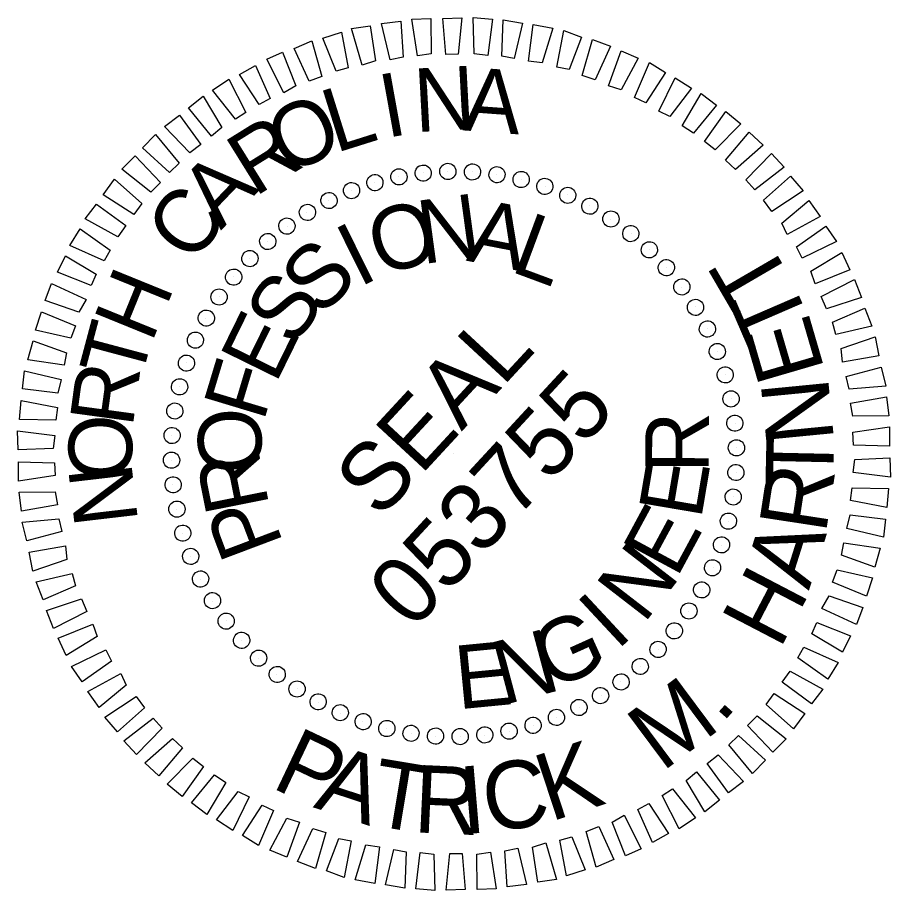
# Model space of a CAD drawing. Extents: x 1768274 to 1769121, y 999922 to 1000687.
# Drawn here: x 1769000.709 to 1769001.89, y 1000302.108 to 1000303.288 of the extents above; entities that cross this region are included whole.
import ezdxf

# ---------------------------------------------------------------- set-up
doc = ezdxf.new("R2010")
doc.units = 0
doc.layers.add('E_NCDOT_Terrain_Model_Void', color=7, linetype='Continuous')

msp = doc.modelspace()

# ---------------------------------------------------------------- linework, layer by layer
at = {"layer": 'E_NCDOT_Terrain_Model_Void'}
for p, q in [((1769001.2586, 1000303.0787), (1769001.2586, 1000303.0787)), ((1769001.2914, 1000303.0805), (1769001.2914, 1000303.0805)), ((1769001.3254, 1000303.0802), (1769001.3254, 1000303.0802)), ((1769001.3579, 1000303.0761), (1769001.3579, 1000303.0761)), ((1769001.1928, 1000303.0658), (1769001.1928, 1000303.0658)), ((1769001.2254, 1000303.073), (1769001.2254, 1000303.073)), ((1769001.391, 1000303.0693), (1769001.391, 1000303.0693)), ((1769001.1614, 1000303.0543), (1769001.1614, 1000303.0543)), ((1769001.4232, 1000303.0603), (1769001.4232, 1000303.0603)), ((1769001.1307, 1000303.0413), (1769001.1307, 1000303.0413)), ((1769001.4538, 1000303.0486), (1769001.4538, 1000303.0486)), ((1769001.4835, 1000303.0336), (1769001.4835, 1000303.0336)), ((1769001.1011, 1000303.025), (1769001.1011, 1000303.025)), ((1769001.5123, 1000303.0153), (1769001.5123, 1000303.0153)), ((1769001.0744, 1000303.0062), (1769001.0744, 1000303.0062)), ((1769001.5394, 1000302.9964), (1769001.5394, 1000302.9964)), ((1769001.0482, 1000302.9857), (1769001.0482, 1000302.9857)), ((1769001.5646, 1000302.9742), (1769001.5646, 1000302.9742)), ((1769001.0238, 1000302.9627), (1769001.0238, 1000302.9627)), ((1769001.5876, 1000302.9498), (1769001.5876, 1000302.9498)), ((1769001.0016, 1000302.9375), (1769001.0016, 1000302.9375)), ((1769001.6081, 1000302.9237), (1769001.6081, 1000302.9237)), ((1769000.9827, 1000302.9104), (1769000.9827, 1000302.9104)), ((1769001.6269, 1000302.8969), (1769001.6269, 1000302.8969)), ((1769000.9644, 1000302.8816), (1769000.9644, 1000302.8816)), ((1769001.6432, 1000302.8674), (1769001.6432, 1000302.8674)), ((1769000.9494, 1000302.8519), (1769000.9494, 1000302.8519)), ((1769001.6562, 1000302.8366), (1769001.6562, 1000302.8366)), ((1769000.9377, 1000302.8213), (1769000.9377, 1000302.8213)), ((1769001.6677, 1000302.8052), (1769001.6677, 1000302.8052)), ((1769000.9287, 1000302.7891), (1769000.9287, 1000302.7891)), ((1769001.6749, 1000302.7726), (1769001.6749, 1000302.7726)), ((1769000.9219, 1000302.756), (1769000.9219, 1000302.756)), ((1769001.6805, 1000302.7394), (1769001.6805, 1000302.7394)), ((1769000.9178, 1000302.7235), (1769000.9178, 1000302.7235)), ((1769001.2999, 1000302.6981), (1769001.2999, 1000302.6981)), ((1769001.6824, 1000302.7066), (1769001.6824, 1000302.7066)), ((1769000.9175, 1000302.6895), (1769000.9175, 1000302.6895)), ((1769001.6821, 1000302.6726), (1769001.6821, 1000302.6726)), ((1769000.9194, 1000302.6567), (1769000.9194, 1000302.6567)), ((1769001.678, 1000302.6401), (1769001.678, 1000302.6401)), ((1769000.925, 1000302.6235), (1769000.925, 1000302.6235)), ((1769001.6712, 1000302.607), (1769001.6712, 1000302.607)), ((1769000.9322, 1000302.5909), (1769000.9322, 1000302.5909)), ((1769001.6622, 1000302.5748), (1769001.6622, 1000302.5748)), ((1769000.9437, 1000302.5595), (1769000.9437, 1000302.5595)), ((1769001.6505, 1000302.5442), (1769001.6505, 1000302.5442)), ((1769000.9567, 1000302.5288), (1769000.9567, 1000302.5288)), ((1769001.6355, 1000302.5145), (1769001.6355, 1000302.5145)), ((1769000.973, 1000302.4992), (1769000.973, 1000302.4992)), ((1769001.6172, 1000302.4857), (1769001.6172, 1000302.4857)), ((1769000.9918, 1000302.4725), (1769000.9918, 1000302.4725)), ((1769001.5983, 1000302.4586), (1769001.5983, 1000302.4586)), ((1769001.0123, 1000302.4463), (1769001.0123, 1000302.4463)), ((1769001.5761, 1000302.4334), (1769001.5761, 1000302.4334)), ((1769001.0353, 1000302.4219), (1769001.0353, 1000302.4219)), ((1769001.5517, 1000302.4104), (1769001.5517, 1000302.4104)), ((1769001.0605, 1000302.3997), (1769001.0605, 1000302.3997)), ((1769001.5255, 1000302.3899), (1769001.5255, 1000302.3899)), ((1769001.0876, 1000302.3808), (1769001.0876, 1000302.3808)), ((1769001.4988, 1000302.3711), (1769001.4988, 1000302.3711)), ((1769001.1164, 1000302.3625), (1769001.1164, 1000302.3625)), ((1769001.4692, 1000302.3548), (1769001.4692, 1000302.3548)), ((1769001.1461, 1000302.3475), (1769001.1461, 1000302.3475)), ((1769001.4385, 1000302.3418), (1769001.4385, 1000302.3418)), ((1769001.1767, 1000302.3358), (1769001.1767, 1000302.3358)), ((1769001.4071, 1000302.3303), (1769001.4071, 1000302.3303)), ((1769001.2089, 1000302.3268), (1769001.2089, 1000302.3268)), ((1769001.242, 1000302.32), (1769001.242, 1000302.32)), ((1769001.3413, 1000302.3175), (1769001.3413, 1000302.3175)), ((1769001.3745, 1000302.3231), (1769001.3745, 1000302.3231)), ((1769001.2745, 1000302.3159), (1769001.2745, 1000302.3159)), ((1769001.3085, 1000302.3156), (1769001.3085, 1000302.3156))]:
    msp.add_line(p, q, dxfattribs=at)
for points in [[(1769001.2508, 1000303.2363), (1769001.2429, 1000303.2861), (1769001.2687, 1000303.2871), (1769001.269, 1000303.2392)], [(1769001.289, 1000303.2383), (1769001.2849, 1000303.2867), (1769001.3107, 1000303.2877), (1769001.3057, 1000303.2385)], [(1769001.3272, 1000303.2393), (1769001.3258, 1000303.2883), (1769001.3518, 1000303.2861), (1769001.3456, 1000303.2368)], [(1769001.1758, 1000303.2237), (1769001.1614, 1000303.2732), (1769001.1866, 1000303.2769), (1769001.1939, 1000303.2298)], [(1769001.2138, 1000303.2311), (1769001.2021, 1000303.2802), (1769001.2279, 1000303.2834), (1769001.2314, 1000303.2345)], [(1769001.3645, 1000303.2359), (1769001.3664, 1000303.2851), (1769001.3924, 1000303.2807), (1769001.3814, 1000303.2328)], [(1769001.4009, 1000303.2293), (1769001.4071, 1000303.2786), (1769001.4337, 1000303.2737), (1769001.4193, 1000303.2268)], [(1769001.1405, 1000303.2158), (1769001.1226, 1000303.2604), (1769001.1476, 1000303.2684), (1769001.157, 1000303.2202)], [(1769001.439, 1000303.2211), (1769001.4483, 1000303.2705), (1769001.4724, 1000303.2617), (1769001.4558, 1000303.2179)], [(1769001.1039, 1000303.202), (1769001.0838, 1000303.2465), (1769001.1076, 1000303.2566), (1769001.1214, 1000303.2086)], [(1769001.4734, 1000303.21), (1769001.4871, 1000303.2585), (1769001.5117, 1000303.2493), (1769001.4908, 1000303.2042)], [(1769001.07, 1000303.1866), (1769001.0466, 1000303.2321), (1769001.0678, 1000303.2415), (1769001.0858, 1000303.1959)], [(1769001.509, 1000303.1958), (1769001.526, 1000303.2433), (1769001.549, 1000303.2335), (1769001.5259, 1000303.1905)], [(1769001.5441, 1000303.1799), (1769001.5643, 1000303.2276), (1769001.5859, 1000303.2139), (1769001.5595, 1000303.173)], [(1769001.0366, 1000303.1707), (1769001.0097, 1000303.2112), (1769001.0313, 1000303.2234), (1769001.0514, 1000303.1789)], [(1769001.0045, 1000303.1506), (1769000.9733, 1000303.1898), (1769000.9954, 1000303.2047), (1769001.0182, 1000303.1598)], [(1769001.5771, 1000303.1618), (1769001.5991, 1000303.2069), (1769001.6212, 1000303.1926), (1769001.592, 1000303.1543)], [(1769000.972, 1000303.1278), (1769000.9408, 1000303.1659), (1769000.9607, 1000303.1818), (1769000.9861, 1000303.1396)], [(1769001.6087, 1000303.142), (1769001.6344, 1000303.1856), (1769001.655, 1000303.1697), (1769001.6241, 1000303.1318)], [(1769000.9427, 1000303.1051), (1769000.9084, 1000303.1409), (1769000.9288, 1000303.1563), (1769000.9573, 1000303.1164)], [(1769001.6386, 1000303.1205), (1769001.6677, 1000303.161), (1769001.6878, 1000303.1446), (1769001.6531, 1000303.1093)], [(1769001.6671, 1000303.0953), (1769001.699, 1000303.1332), (1769001.7181, 1000303.1156), (1769001.6805, 1000303.0828)], [(1769000.9152, 1000303.0786), (1769000.8788, 1000303.1122), (1769000.8964, 1000303.1302), (1769000.9281, 1000303.0915)], [(1769000.8898, 1000303.0523), (1769000.8508, 1000303.0831), (1769000.8685, 1000303.1011), (1769000.9028, 1000303.0652)], [(1769001.6946, 1000303.0688), (1769001.7293, 1000303.1042), (1769001.7467, 1000303.086), (1769001.7069, 1000303.0553)], [(1769001.7188, 1000303.0412), (1769001.7553, 1000303.0739), (1769001.7722, 1000303.0541), (1769001.7297, 1000303.026)], [(1769000.8667, 1000303.0217), (1769000.8252, 1000303.0487), (1769000.8406, 1000303.0698), (1769000.8775, 1000303.0367)], [(1769001.7432, 1000303.0104), (1769001.7797, 1000303.0409), (1769001.7951, 1000303.0194), (1769001.7508, 1000302.995)], [(1769000.8453, 1000302.9918), (1769000.8012, 1000303.0159), (1769000.8166, 1000303.0359), (1769000.856, 1000303.0068)], [(1769000.8266, 1000302.9592), (1769000.7805, 1000302.9801), (1769000.7942, 1000303.0027), (1769000.8347, 1000302.9736)], [(1769001.7633, 1000302.9783), (1769001.8027, 1000303.0062), (1769001.8175, 1000302.9853), (1769001.771, 1000302.9629)], [(1769001.7824, 1000302.9451), (1769001.8246, 1000302.9704), (1769001.8352, 1000302.9471), (1769001.7885, 1000302.9281)], [(1769000.809, 1000302.9257), (1769000.7636, 1000302.9438), (1769000.7746, 1000302.9658), (1769000.816, 1000302.941)], [(1769001.7967, 1000302.9111), (1769001.8416, 1000302.9339), (1769001.8512, 1000302.9095), (1769001.8038, 1000302.8942)], [(1769000.7927, 1000302.89), (1769000.7468, 1000302.9054), (1769000.7556, 1000302.9284), (1769000.8022, 1000302.9071)], [(1769000.7817, 1000302.8545), (1769000.7338, 1000302.8656), (1769000.742, 1000302.8901), (1769000.788, 1000302.8715)], [(1769001.8121, 1000302.8761), (1769001.8556, 1000302.8951), (1769001.8651, 1000302.8707), (1769001.8165, 1000302.8596)], [(1769000.7728, 1000302.818), (1769000.7235, 1000302.8253), (1769000.7306, 1000302.8509), (1769000.776, 1000302.8349)], [(1769001.8237, 1000302.8405), (1769001.8695, 1000302.8563), (1769001.8748, 1000302.8306), (1769001.8255, 1000302.8222)], [(1769001.8306, 1000302.803), (1769001.8776, 1000302.8156), (1769001.884, 1000302.79), (1769001.8345, 1000302.7859)], [(1769000.7641, 1000302.7805), (1769000.7164, 1000302.7862), (1769000.7192, 1000302.8105), (1769000.7687, 1000302.799)], [(1769000.7612, 1000302.7437), (1769000.7121, 1000302.7445), (1769000.7143, 1000302.7705), (1769000.7638, 1000302.7611)], [(1769001.8364, 1000302.7666), (1769001.8851, 1000302.7755), (1769001.8882, 1000302.7498), (1769001.8392, 1000302.7494)], [(1769001.8395, 1000302.7274), (1769001.8888, 1000302.7347), (1769001.8888, 1000302.7088), (1769001.8402, 1000302.7101)], [(1769000.7579, 1000302.7053), (1769000.7105, 1000302.7035), (1769000.7095, 1000302.7293), (1769000.7599, 1000302.7232)], [(1769000.7604, 1000302.6688), (1769000.7111, 1000302.6614), (1769000.7111, 1000302.6873), (1769000.7597, 1000302.686)], [(1769001.842, 1000302.6908), (1769001.8894, 1000302.6927), (1769001.8904, 1000302.6668), (1769001.84, 1000302.6729)], [(1769001.8387, 1000302.6524), (1769001.8878, 1000302.6516), (1769001.8856, 1000302.6257), (1769001.8361, 1000302.635)], [(1769000.7635, 1000302.6295), (1769000.7148, 1000302.6206), (1769000.7117, 1000302.6464), (1769000.7607, 1000302.6467)], [(1769001.8358, 1000302.6156), (1769001.8835, 1000302.6099), (1769001.8807, 1000302.5856), (1769001.8312, 1000302.5971)], [(1769000.7693, 1000302.5931), (1769000.7223, 1000302.5805), (1769000.7159, 1000302.6061), (1769000.7654, 1000302.6102)], [(1769001.8271, 1000302.5781), (1769001.8764, 1000302.5708), (1769001.8693, 1000302.5452), (1769001.8239, 1000302.5612)], [(1769000.7762, 1000302.5556), (1769000.7304, 1000302.5398), (1769000.7251, 1000302.5655), (1769000.7744, 1000302.5739)], [(1769000.7878, 1000302.52), (1769000.7443, 1000302.501), (1769000.7347, 1000302.5254), (1769000.7834, 1000302.5365)], [(1769001.8182, 1000302.5416), (1769001.8661, 1000302.5306), (1769001.8579, 1000302.506), (1769001.8119, 1000302.5246)], [(1769000.8032, 1000302.485), (1769000.7583, 1000302.4622), (1769000.7487, 1000302.4866), (1769000.7961, 1000302.502)], [(1769001.8072, 1000302.5061), (1769001.8531, 1000302.4907), (1769001.8443, 1000302.4677), (1769001.7977, 1000302.489)], [(1769000.8175, 1000302.4511), (1769000.7753, 1000302.4257), (1769000.7647, 1000302.449), (1769000.8114, 1000302.4681)], [(1769001.7909, 1000302.4704), (1769001.8363, 1000302.4523), (1769001.8253, 1000302.4303), (1769001.7839, 1000302.4551)], [(1769001.7733, 1000302.4369), (1769001.8194, 1000302.416), (1769001.8057, 1000302.3934), (1769001.7652, 1000302.4225)], [(1769000.8366, 1000302.4178), (1769000.7972, 1000302.3899), (1769000.7824, 1000302.4109), (1769000.8289, 1000302.4332)], [(1769000.8567, 1000302.3857), (1769000.8202, 1000302.3552), (1769000.8047, 1000302.3767), (1769000.8491, 1000302.4011)], [(1769001.7546, 1000302.4043), (1769001.7987, 1000302.3802), (1769001.7833, 1000302.3602), (1769001.7439, 1000302.3894)], [(1769000.8811, 1000302.3549), (1769000.8446, 1000302.3222), (1769000.8277, 1000302.342), (1769000.8702, 1000302.3701)], [(1769001.7332, 1000302.3744), (1769001.7747, 1000302.3474), (1769001.7593, 1000302.3263), (1769001.7224, 1000302.3594)], [(1769001.7101, 1000302.3438), (1769001.7491, 1000302.313), (1769001.7314, 1000302.2951), (1769001.6971, 1000302.3309)], [(1769000.9053, 1000302.3273), (1769000.8706, 1000302.2919), (1769000.8532, 1000302.3101), (1769000.893, 1000302.3408)], [(1769001.6847, 1000302.3175), (1769001.7211, 1000302.2839), (1769001.7035, 1000302.2659), (1769001.6718, 1000302.3046)], [(1769000.9328, 1000302.3009), (1769000.9009, 1000302.2629), (1769000.8818, 1000302.2805), (1769000.9194, 1000302.3133)], [(1769000.9613, 1000302.2756), (1769000.9322, 1000302.2351), (1769000.9121, 1000302.2515), (1769000.9468, 1000302.2869)], [(1769001.6572, 1000302.2911), (1769001.6915, 1000302.2552), (1769001.6711, 1000302.2399), (1769001.6426, 1000302.2797)], [(1769000.9912, 1000302.2541), (1769000.9655, 1000302.2105), (1769000.9449, 1000302.2264), (1769000.9758, 1000302.2643)], [(1769001.6279, 1000302.2683), (1769001.6591, 1000302.2302), (1769001.6392, 1000302.2143), (1769001.6138, 1000302.2565)], [(1769001.0228, 1000302.2343), (1769001.0008, 1000302.1892), (1769000.9787, 1000302.2035), (1769001.0079, 1000302.2418)], [(1769001.5954, 1000302.2455), (1769001.6266, 1000302.2063), (1769001.6045, 1000302.1914), (1769001.5817, 1000302.2363)], [(1769001.0558, 1000302.2162), (1769001.0356, 1000302.1685), (1769001.014, 1000302.1822), (1769001.0404, 1000302.2232)], [(1769001.5633, 1000302.2254), (1769001.5902, 1000302.1849), (1769001.5686, 1000302.1728), (1769001.5485, 1000302.2172)], [(1769001.0909, 1000302.2003), (1769001.0739, 1000302.1528), (1769001.0509, 1000302.1626), (1769001.074, 1000302.2056)], [(1769001.5299, 1000302.2095), (1769001.5533, 1000302.1641), (1769001.5321, 1000302.1546), (1769001.5141, 1000302.2003)], [(1769001.1265, 1000302.1861), (1769001.1128, 1000302.1376), (1769001.0882, 1000302.1469), (1769001.1091, 1000302.1919)], [(1769001.496, 1000302.1942), (1769001.5161, 1000302.1497), (1769001.4923, 1000302.1396), (1769001.4785, 1000302.1875)], [(1769001.1609, 1000302.1751), (1769001.1516, 1000302.1256), (1769001.1275, 1000302.1344), (1769001.1441, 1000302.1782)], [(1769001.4594, 1000302.1803), (1769001.4773, 1000302.1357), (1769001.4523, 1000302.1277), (1769001.4429, 1000302.1759)], [(1769001.199, 1000302.1668), (1769001.1928, 1000302.1175), (1769001.1662, 1000302.1224), (1769001.1806, 1000302.1694)], [(1769001.3861, 1000302.165), (1769001.3978, 1000302.1159), (1769001.372, 1000302.1127), (1769001.3685, 1000302.1617)], [(1769001.4241, 1000302.1725), (1769001.4385, 1000302.1229), (1769001.4133, 1000302.1192), (1769001.406, 1000302.1664)], [(1769001.2354, 1000302.1602), (1769001.2335, 1000302.1111), (1769001.2075, 1000302.1154), (1769001.2185, 1000302.1633)], [(1769001.2727, 1000302.1568), (1769001.2741, 1000302.1078), (1769001.2481, 1000302.11), (1769001.2543, 1000302.1593)], [(1769001.3109, 1000302.1578), (1769001.315, 1000302.1094), (1769001.2892, 1000302.1084), (1769001.2942, 1000302.1577)], [(1769001.3491, 1000302.1598), (1769001.357, 1000302.11), (1769001.3312, 1000302.109), (1769001.3309, 1000302.1569)]]:
    msp.add_lwpolyline(points, close=True, dxfattribs=at)
for centre, major_axis in [((1769001.2583, 1000303.0779), (-0.0012, 0.0109)), ((1769001.2916, 1000303.0801), (-0.0002, 0.011)), ((1769001.3249, 1000303.0794), (0.0007, 0.0109)), ((1769001.3581, 1000303.0757), (0.0017, 0.0108)), ((1769001.193, 1000303.0649), (-0.0031, 0.0105)), ((1769001.2254, 1000303.0728), (-0.0021, 0.0108)), ((1769001.3908, 1000303.0692), (0.0026, 0.0107)), ((1769001.1614, 1000303.0542), (-0.004, 0.0102)), ((1769001.4228, 1000303.0599), (0.0035, 0.0104)), ((1769001.1309, 1000303.0408), (-0.00485, 0.00984)), ((1769001.4538, 1000303.0478), (0.0044, 0.01)), ((1769001.4837, 1000303.0331), (0.00528, 0.00962)), ((1769001.1017, 1000303.0247), (-0.00569, 0.00938)), ((1769001.5122, 1000303.0158), (0.00609, 0.00912)), ((1769001.074, 1000303.0062), (-0.00649, 0.00885)), ((1769001.5391, 1000302.9961), (0.00687, 0.00856)), ((1769001.048, 1000302.9854), (-0.00723, 0.00825)), ((1769001.5642, 1000302.9741), (0.00759, 0.00792)), ((1769001.0239, 1000302.9623), (-0.00792, 0.00759)), ((1769001.5872, 1000302.95), (0.00825, 0.00723)), ((1769001.0019, 1000302.9372), (-0.00856, 0.00687)), ((1769001.6081, 1000302.924), (0.00885, 0.00649)), ((1769000.9822, 1000302.9103), (-0.00912, 0.00609)), ((1769001.6266, 1000302.8963), (0.00938, 0.00569)), ((1769000.9649, 1000302.8818), (-0.00962, 0.00528)), ((1769001.6427, 1000302.8671), (0.00984, 0.00485)), ((1769000.9502, 1000302.852), (-0.01, 0.0044)), ((1769001.6561, 1000302.8366), (0.0102, 0.004)), ((1769000.9381, 1000302.8209), (-0.0104, 0.0035)), ((1769001.6668, 1000302.805), (0.0105, 0.0031)), ((1769000.9288, 1000302.7889), (-0.0107, 0.0026)), ((1769001.6747, 1000302.7726), (0.0108, 0.0021)), ((1769000.9223, 1000302.7562), (-0.0108, 0.0017)), ((1769001.6798, 1000302.7397), (0.0109, 0.0012)), ((1769000.9186, 1000302.723), (-0.0109, 0.0007)), ((1769001.682, 1000302.7064), (0.011, 0.0002)), ((1769000.9179, 1000302.6897), (-0.011, -0.0002)), ((1769001.6813, 1000302.6731), (0.0109, -0.0007)), ((1769000.9201, 1000302.6564), (-0.0109, -0.0012)), ((1769001.6776, 1000302.6399), (0.0108, -0.0017)), ((1769000.9252, 1000302.6235), (-0.0108, -0.0021)), ((1769001.6711, 1000302.6072), (0.0107, -0.0026)), ((1769000.9331, 1000302.5911), (-0.0105, -0.0031)), ((1769001.6618, 1000302.5752), (0.0104, -0.0035)), ((1769000.9438, 1000302.5596), (-0.0102, -0.004)), ((1769001.6497, 1000302.5442), (0.01, -0.0044)), ((1769000.9572, 1000302.529), (-0.00984, -0.00485)), ((1769001.635, 1000302.5143), (0.00962, -0.00528)), ((1769000.9733, 1000302.4998), (-0.00938, -0.00569)), ((1769001.6177, 1000302.4858), (0.00912, -0.00609)), ((1769000.9918, 1000302.4721), (-0.00885, -0.00649)), ((1769001.598, 1000302.4589), (0.00856, -0.00687)), ((1769001.0127, 1000302.4461), (-0.00825, -0.00723)), ((1769001.576, 1000302.4338), (0.00792, -0.00759)), ((1769001.0357, 1000302.422), (-0.00759, -0.00792)), ((1769001.0608, 1000302.4), (-0.00687, -0.00856)), ((1769001.5519, 1000302.4108), (0.00723, -0.00825)), ((1769001.5259, 1000302.3899), (0.00649, -0.00885)), ((1769001.0877, 1000302.3803), (-0.00609, -0.00912)), ((1769001.4982, 1000302.3714), (0.00569, -0.00938)), ((1769001.1162, 1000302.363), (-0.00528, -0.00962)), ((1769001.469, 1000302.3553), (0.00485, -0.00984)), ((1769001.1461, 1000302.3483), (-0.0044, -0.01)), ((1769001.4385, 1000302.3419), (0.004, -0.0102)), ((1769001.1771, 1000302.3362), (-0.0035, -0.0104)), ((1769001.4069, 1000302.3312), (0.0031, -0.0105)), ((1769001.2091, 1000302.3269), (-0.0026, -0.0107)), ((1769001.2418, 1000302.3204), (-0.0017, -0.0108)), ((1769001.3416, 1000302.3182), (0.0012, -0.0109)), ((1769001.3745, 1000302.3233), (0.0021, -0.0108)), ((1769001.275, 1000302.3167), (-0.0007, -0.0109)), ((1769001.3083, 1000302.316), (0.0002, -0.011))]:
    msp.add_ellipse(centre, major_axis=major_axis, ratio=0.999708, dxfattribs=at)

# ---------------------------------------------------------------- texts
for s, height, rotation, p in [('N', 0.0859, 3.0701, (1769001.2478, 1000303.1332)), ('A', 0.0859, 355.8684, (1769001.3113, 1000303.1357)), ('I', 0.0859, 10.2714, (1769001.2082, 1000303.1252)), ('L', 0.0859, 17.4721, (1769001.1395, 1000303.1047)), ('O', 0.0859, 24.6724, (1769001.0733, 1000303.0746)), ('R', 0.0859, 31.8723, (1769001.0302, 1000303.0449)), ('A', 0.0859, 46.2715, (1769000.9846, 1000303)), ('C', 0.0859, 53.4711, (1769000.9471, 1000302.9527)), ('N', 0.0859, 7.7278, (1769001.257, 1000302.9546)), ('O', 0.0859, 17.0847, (1769001.2, 1000302.9378)), ('A', 0.0859, 349.0115, (1769001.3155, 1000302.9596)), ('L', 0.0859, 339.6521, (1769001.3743, 1000302.9457)), ('I', 0.0859, 26.4408, (1769001.1714, 1000302.9227)), ('S', 0.0859, 45.1516, (1769001.1191, 1000302.8818)), ('T', 0.0914, 120.207, (1769001.7597, 1000302.9289)), ('H', 0.0859, 67.8707, (1769000.8908, 1000302.8469)), ('S', 0.0859, 54.5068, (1769001.0825, 1000302.841)), ('T', 0.0914, 113.4067, (1769001.7838, 1000302.8728)), ('E', 0.0859, 63.8623, (1769001.0585, 1000302.7915)), ('E', 0.0914, 106.2974, (1769001.8017, 1000302.8116)), ('T', 0.0859, 75.071, (1769000.8757, 1000302.7935)), ('SEAL', 0.09139, 47.2512, (1769001.1995, 1000302.6084)), ('F', 0.0859, 73.2183, (1769001.0422, 1000302.7402)), ('R', 0.0859, 82.2717, (1769000.8651, 1000302.7327)), ('053755', 0.09139, 47.2512, (1769001.2444, 1000302.4582)), ('N', 0.0914, 95.5715, (1769001.8141, 1000302.7162)), ('O', 0.0859, 91.9325, (1769001.0411, 1000302.6728)), ('O', 0.0859, 89.473, (1769000.8642, 1000302.6621)), ('R', 0.0859, 89.7326, (1769001.6444, 1000302.6722)), ('T', 0.0914, 88.7713, (1769001.8126, 1000302.6552)), ('R', 0.0859, 101.2909, (1769001.0504, 1000302.6279)), ('E', 0.0859, 80.3753, (1769001.634, 1000302.6082)), ('N', 0.0859, 96.6747, (1769000.8728, 1000302.6063)), ('R', 0.0914, 81.291, (1769001.8027, 1000302.5888)), ('P', 0.0859, 110.6501, (1769001.0697, 1000302.5769)), ('E', 0.0859, 61.663, (1769001.601, 1000302.5288)), ('A', 0.0914, 72.4507, (1769001.7799, 1000302.5129)), ('N', 0.0859, 52.3076, (1769001.5565, 1000302.4672)), ('H', 0.0914, 62.4668, (1769001.7405, 1000302.4325)), ('I', 0.0859, 42.9524, (1769001.5201, 1000302.4312)), ('G', 0.0859, 24.2415, (1769001.4311, 1000302.3776)), ('N', 0.0859, 14.8852, (1769001.3667, 1000302.3584)), ('E', 0.0859, 5.5281, (1769001.3054, 1000302.3527)), ('M', 0.0914, 36.7031, (1769001.5813, 1000302.2673)), ('.', 0.0914, 48.2326, (1769001.6617, 1000302.3323)), ('P', 0.0914, 334.6046, (1769001.051, 1000302.2479)), ('K', 0.0914, 18.2189, (1769001.4302, 1000302.2004)), ('A', 0.0914, 341.7139, (1769001.1086, 1000302.2205)), ('T', 0.0914, 350.5543, (1769001.1843, 1000302.1968)), ('C', 0.0914, 8.6367, (1769001.3456, 1000302.1856)), ('R', 0.0914, 357.3545, (1769001.2444, 1000302.1866)), ('I', 0.0914, 4.8347, (1769001.3115, 1000302.1837))]:
    msp.add_text(s, height=height, rotation=rotation, dxfattribs=at).set_placement(p)

doc.saveas('drawing.dxf')
